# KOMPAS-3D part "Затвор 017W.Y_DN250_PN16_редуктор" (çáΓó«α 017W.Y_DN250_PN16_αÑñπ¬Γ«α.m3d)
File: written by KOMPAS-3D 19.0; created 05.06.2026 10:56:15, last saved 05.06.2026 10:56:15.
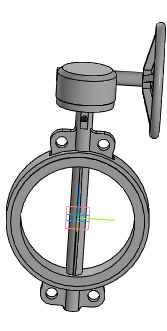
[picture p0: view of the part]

Document properties: Автор: Энергия; Полное имя файла: ..\..\..\3d для проектировщиков\x.x Тип 017W.Y(S) Затвор дисковый поворотный межфланцевый\Затвор 017W.Y(S)_DN50-DN1200_редуктор\Затвор 017W.Y_DN250_PN16_редуктор.a3d

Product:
- Part/product: Затвор 017W.Y_DN250_PN16_редуктор
    Масса: 31.8274

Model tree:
1. Операция без истории:1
